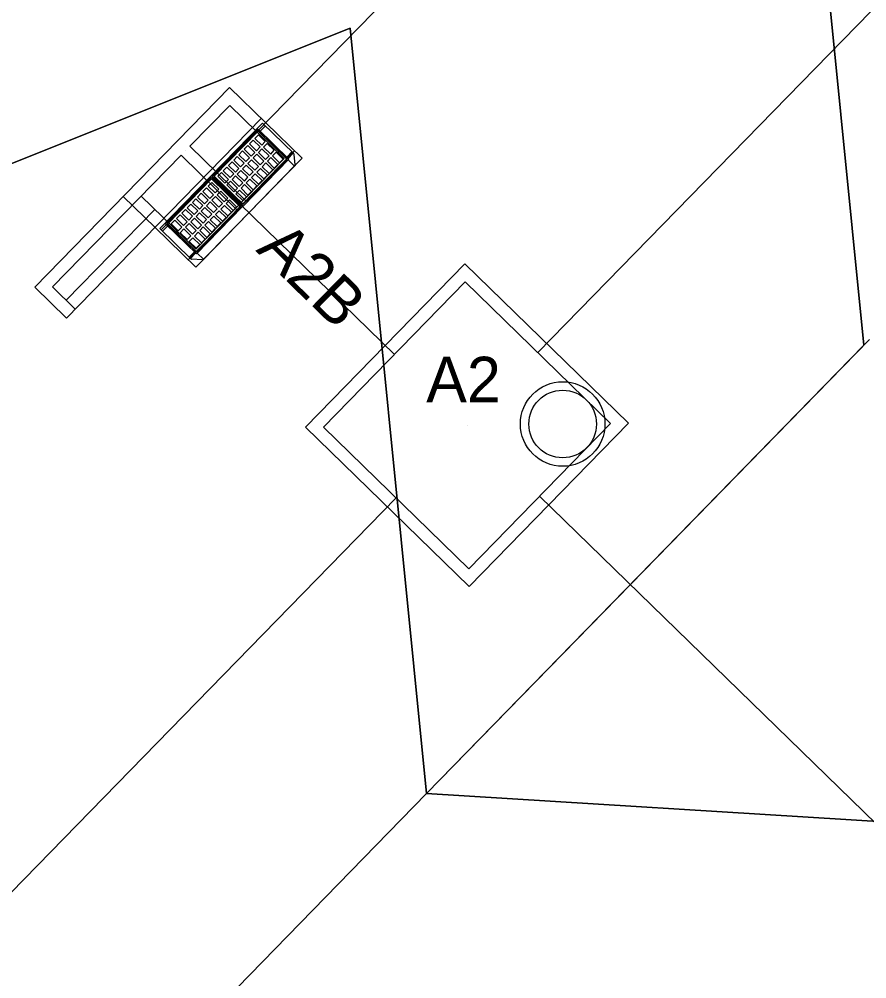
# Model space of a CAD drawing. Extents: x 2251012 to 2259557, y 13786786 to 13792525.
# Drawn here: x 2254858.7 to 2254892.11, y 13790745.59 to 13790783.43 of the extents above; entities that cross this region are included whole.
import ezdxf

# ---------------------------------------------------------------- set-up
doc = ezdxf.new("R2010")
doc.units = 0
for name, color, linetype in [('D_BOXES_1', 7, 'Continuous'), ('D_DRAIN_MISC', 7, 'Continuous'), ('D_DRAIN_NOTES_1', 7, 'Continuous'), ('D_DRN_AREA_X', 7, 'Continuous'), ('D_INLET_1', 7, 'Continuous'), ('D_PIPES_1', 7, 'Continuous')]:
    doc.layers.add(name, color=color, linetype=linetype)

msp = doc.modelspace()

# ---------------------------------------------------------------- linework, layer by layer
at = {"layer": 'D_BOXES_1'}
for p, q in [((2254879.145, 13790770.287), (2254992.252, 13790886.265)), ((2254701.107, 13790587.73), (2254873.56, 13790764.56))]:
    msp.add_line(p, q, dxfattribs=at)
at = {"layer": 'D_DRAIN_MISC'}
for p, q in [((2254868.075, 13790778.988), (2254868.075, 13790778.988)), ((2254865.256, 13790778.245), (2254865.256, 13790778.245)), ((2254866.151, 13790777.373), (2254866.151, 13790777.373)), ((2254867.404, 13790776.151), (2254867.404, 13790776.151)), ((2254864.584, 13790775.408), (2254864.584, 13790775.408)), ((2254873.489, 13790770.216), (2254873.489, 13790770.216)), ((2254879.145, 13790770.287), (2254879.145, 13790770.287)), ((2254876.353, 13790767.423), (2254876.353, 13790767.423)), ((2254873.56, 13790764.56), (2254873.56, 13790764.56)), ((2254879.216, 13790764.631), (2254879.216, 13790764.631))]:
    msp.add_line(p, q, dxfattribs=at)
at = {"layer": 'D_DRN_AREA_X'}
for p, q in [((2254889.021, 13790800.465), (2254891.998, 13790770.575)), ((2254891.998, 13790770.575), (2254889.021, 13790800.465)), ((2254871.751, 13790783.085), (2254856.243, 13790776.881)), ((2254856.243, 13790776.881), (2254871.751, 13790783.085)), ((2254874.758, 13790752.898), (2254871.751, 13790783.085)), ((2254871.751, 13790783.085), (2254874.758, 13790752.898)), ((2254892.224, 13790770.808), (2254881.752, 13790760.069)), ((2254891.998, 13790770.575), (2254892.224, 13790770.808)), ((2254874.758, 13790752.898), (2254891.998, 13790770.575)), ((2254881.752, 13790760.069), (2254874.758, 13790752.898)), ((2254874.758, 13790752.898), (2254731.655, 13790606.163)), ((2254832.878, 13790709.955), (2254874.758, 13790752.898)), ((2254905.36, 13790751.006), (2254874.758, 13790752.898)), ((2254874.758, 13790752.898), (2254905.36, 13790751.006))]:
    msp.add_line(p, q, dxfattribs=at)
at = {"layer": 'D_INLET_1'}
for p, q in [((2254866.993, 13790780.742), (2254859.312, 13790772.867)), ((2254869.856, 13790777.949), (2254866.993, 13790780.742)), ((2254867.001, 13790780.035), (2254865.43, 13790778.424)), ((2254869.149, 13790777.941), (2254867.001, 13790780.035)), ((2254868.245, 13790779.52), (2254860.565, 13790771.645)), ((2254868.294, 13790779.334), (2254865.202, 13790776.164)), ((2254868.115, 13790779.1), (2254866.309, 13790777.248)), ((2254869.333, 13790777.913), (2254868.115, 13790779.1)), ((2254868.149, 13790779.067), (2254868.353, 13790779.276)), ((2254868.2, 13790779.017), (2254868.404, 13790779.226)), ((2254869.523, 13790778.135), (2254868.294, 13790779.334)), ((2254868.12, 13790779.037), (2254866.372, 13790777.244)), ((2254868.118, 13790779.017), (2254866.391, 13790777.247)), ((2254868.129, 13790778.875), (2254867.987, 13790778.73)), ((2254867.987, 13790778.73), (2254868.261, 13790778.462)), ((2254869.25, 13790777.913), (2254868.118, 13790779.017)), ((2254869.27, 13790777.916), (2254868.12, 13790779.037)), ((2254868.403, 13790778.608), (2254868.129, 13790778.875)), ((2254865.43, 13790778.424), (2254867.635, 13790776.274)), ((2254867.714, 13790778.45), (2254867.572, 13790778.304)), ((2254867.572, 13790778.304), (2254867.846, 13790778.036)), ((2254867.714, 13790778.45), (2254867.988, 13790778.182)), ((2254867.921, 13790778.663), (2254867.779, 13790778.517)), ((2254867.779, 13790778.517), (2254868.054, 13790778.249)), ((2254867.921, 13790778.663), (2254868.196, 13790778.395)), ((2254868.054, 13790778.249), (2254868.196, 13790778.395)), ((2254868.13, 13790778.174), (2254868.272, 13790778.32)), ((2254868.261, 13790778.462), (2254868.403, 13790778.608)), ((2254868.272, 13790778.32), (2254868.549, 13790778.05)), ((2254868.338, 13790778.387), (2254868.48, 13790778.533)), ((2254868.338, 13790778.387), (2254868.615, 13790778.117)), ((2254868.757, 13790778.263), (2254868.48, 13790778.533)), ((2254865.081, 13790778.066), (2254860.019, 13790772.876)), ((2254865.081, 13790778.066), (2254867.286, 13790775.916)), ((2254869.555, 13790778.243), (2254865.366, 13790773.947)), ((2254869.149, 13790777.941), (2254865.658, 13790774.361)), ((2254869.853, 13790777.952), (2254865.664, 13790773.657)), ((2254869.856, 13790777.949), (2254865.667, 13790773.654)), ((2254867.298, 13790778.024), (2254867.156, 13790777.878)), ((2254867.298, 13790778.024), (2254867.573, 13790777.756)), ((2254867.506, 13790778.237), (2254867.364, 13790778.091)), ((2254867.364, 13790778.091), (2254867.639, 13790777.823)), ((2254867.506, 13790778.237), (2254867.781, 13790777.969)), ((2254869.27, 13790777.916), (2254867.521, 13790776.123)), ((2254867.524, 13790776.143), (2254869.25, 13790777.913)), ((2254869.333, 13790777.913), (2254867.526, 13790776.06)), ((2254867.639, 13790777.823), (2254867.781, 13790777.969)), ((2254867.846, 13790778.036), (2254867.988, 13790778.182)), ((2254867.923, 13790777.962), (2254868.065, 13790778.107)), ((2254867.923, 13790777.962), (2254868.2, 13790777.692)), ((2254868.065, 13790778.107), (2254868.342, 13790777.837)), ((2254868.13, 13790778.174), (2254868.407, 13790777.905)), ((2254868.407, 13790777.905), (2254868.549, 13790778.05)), ((2254868.484, 13790777.83), (2254868.626, 13790777.975)), ((2254868.615, 13790778.117), (2254868.757, 13790778.263)), ((2254868.626, 13790777.975), (2254868.9, 13790777.708)), ((2254868.691, 13790778.043), (2254868.833, 13790778.188)), ((2254868.691, 13790778.043), (2254868.966, 13790777.775)), ((2254869.108, 13790777.92), (2254868.833, 13790778.188)), ((2254868.966, 13790777.775), (2254869.108, 13790777.92)), ((2254869.248, 13790777.996), (2254869.452, 13790778.205)), ((2254869.299, 13790777.946), (2254869.503, 13790778.155)), ((2254869.578, 13790777.691), (2254869.539, 13790778.104)), ((2254869.567, 13790777.659), (2254865.95, 13790773.95)), ((2254866.883, 13790777.598), (2254866.741, 13790777.453)), ((2254866.883, 13790777.598), (2254867.158, 13790777.33)), ((2254867.091, 13790777.811), (2254866.949, 13790777.665)), ((2254866.949, 13790777.665), (2254867.223, 13790777.398)), ((2254867.091, 13790777.811), (2254867.365, 13790777.543)), ((2254867.156, 13790777.878), (2254867.431, 13790777.611)), ((2254867.223, 13790777.398), (2254867.365, 13790777.543)), ((2254867.431, 13790777.611), (2254867.573, 13790777.756)), ((2254867.508, 13790777.536), (2254867.65, 13790777.681)), ((2254867.508, 13790777.536), (2254867.784, 13790777.266)), ((2254867.65, 13790777.681), (2254867.926, 13790777.412)), ((2254869.238, 13790777.86), (2254867.664, 13790776.246)), ((2254867.715, 13790777.749), (2254867.857, 13790777.894)), ((2254867.715, 13790777.749), (2254867.992, 13790777.479)), ((2254867.857, 13790777.894), (2254868.134, 13790777.624)), ((2254867.992, 13790777.479), (2254868.134, 13790777.624)), ((2254868.069, 13790777.404), (2254868.211, 13790777.55)), ((2254868.2, 13790777.692), (2254868.342, 13790777.837)), ((2254868.211, 13790777.55), (2254868.485, 13790777.282)), ((2254868.276, 13790777.617), (2254868.418, 13790777.763)), ((2254868.276, 13790777.617), (2254868.551, 13790777.349)), ((2254868.418, 13790777.763), (2254868.693, 13790777.495)), ((2254868.484, 13790777.83), (2254868.758, 13790777.562)), ((2254868.758, 13790777.562), (2254868.9, 13790777.708)), ((2254869.304, 13790777.883), (2254869.551, 13790777.642)), ((2254864.473, 13790775.365), (2254866.28, 13790777.218)), ((2254864.536, 13790775.362), (2254866.285, 13790777.155)), ((2254867.497, 13790776.03), (2254866.28, 13790777.218)), ((2254867.434, 13790776.034), (2254866.285, 13790777.155)), ((2254867.526, 13790776.06), (2254866.309, 13790777.248)), ((2254867.521, 13790776.123), (2254866.372, 13790777.244)), ((2254867.524, 13790776.143), (2254866.391, 13790777.247)), ((2254866.676, 13790777.385), (2254866.534, 13790777.24)), ((2254866.808, 13790776.972), (2254866.534, 13790777.24)), ((2254866.676, 13790777.385), (2254866.95, 13790777.118)), ((2254866.741, 13790777.453), (2254867.016, 13790777.185)), ((2254867.016, 13790777.185), (2254867.158, 13790777.33)), ((2254867.092, 13790777.11), (2254867.234, 13790777.256)), ((2254867.234, 13790777.256), (2254867.511, 13790776.986)), ((2254867.3, 13790777.323), (2254867.442, 13790777.469)), ((2254867.3, 13790777.323), (2254867.577, 13790777.053)), ((2254867.442, 13790777.469), (2254867.719, 13790777.199)), ((2254867.577, 13790777.053), (2254867.719, 13790777.199)), ((2254867.784, 13790777.266), (2254867.926, 13790777.412)), ((2254867.861, 13790777.191), (2254868.003, 13790777.337)), ((2254867.861, 13790777.191), (2254868.136, 13790776.923)), ((2254868.003, 13790777.337), (2254868.278, 13790777.069)), ((2254868.069, 13790777.404), (2254868.343, 13790777.136)), ((2254868.343, 13790777.136), (2254868.485, 13790777.282)), ((2254868.551, 13790777.349), (2254868.693, 13790777.495)), ((2254864.556, 13790775.365), (2254866.282, 13790777.135)), ((2254865.944, 13790776.635), (2254866.086, 13790776.78)), ((2254866.086, 13790776.78), (2254866.36, 13790776.513)), ((2254866.151, 13790776.848), (2254866.293, 13790776.993)), ((2254866.151, 13790776.848), (2254866.426, 13790776.58)), ((2254867.415, 13790776.031), (2254866.282, 13790777.135)), ((2254866.568, 13790776.725), (2254866.293, 13790776.993)), ((2254866.808, 13790776.972), (2254866.95, 13790777.118)), ((2254866.885, 13790776.897), (2254867.027, 13790777.043)), ((2254867.162, 13790776.627), (2254866.885, 13790776.897)), ((2254867.027, 13790777.043), (2254867.304, 13790776.773)), ((2254867.092, 13790777.11), (2254867.369, 13790776.84)), ((2254867.162, 13790776.627), (2254867.304, 13790776.773)), ((2254867.369, 13790776.84), (2254867.511, 13790776.986)), ((2254867.446, 13790776.765), (2254867.588, 13790776.911)), ((2254867.588, 13790776.911), (2254867.862, 13790776.643)), ((2254867.653, 13790776.978), (2254867.795, 13790777.124)), ((2254867.653, 13790776.978), (2254867.928, 13790776.71)), ((2254867.795, 13790777.124), (2254868.07, 13790776.856)), ((2254867.928, 13790776.71), (2254868.07, 13790776.856)), ((2254868.136, 13790776.923), (2254868.278, 13790777.069)), ((2254864.056, 13790775.225), (2254862.803, 13790776.447)), ((2254865.658, 13790774.361), (2254863.51, 13790776.456)), ((2254865.736, 13790776.422), (2254865.878, 13790776.567)), ((2254865.736, 13790776.422), (2254866.011, 13790776.154)), ((2254865.878, 13790776.567), (2254866.153, 13790776.3)), ((2254865.944, 13790776.635), (2254866.218, 13790776.367)), ((2254866.36, 13790776.513), (2254866.218, 13790776.367)), ((2254866.437, 13790776.438), (2254866.295, 13790776.292)), ((2254866.568, 13790776.725), (2254866.426, 13790776.58)), ((2254866.437, 13790776.438), (2254866.714, 13790776.168)), ((2254866.644, 13790776.651), (2254866.502, 13790776.505)), ((2254866.502, 13790776.505), (2254866.779, 13790776.235)), ((2254866.921, 13790776.381), (2254866.644, 13790776.651)), ((2254867.238, 13790776.553), (2254867.38, 13790776.698)), ((2254867.513, 13790776.285), (2254867.238, 13790776.553)), ((2254867.38, 13790776.698), (2254867.655, 13790776.43)), ((2254867.446, 13790776.765), (2254867.72, 13790776.498)), ((2254867.513, 13790776.285), (2254867.655, 13790776.43)), ((2254867.72, 13790776.498), (2254867.862, 13790776.643)), ((2254865.202, 13790776.164), (2254864.244, 13790775.181)), ((2254865.321, 13790775.996), (2254865.463, 13790776.142)), ((2254865.463, 13790776.142), (2254865.737, 13790775.874)), ((2254865.528, 13790776.209), (2254865.67, 13790776.355)), ((2254865.528, 13790776.209), (2254865.803, 13790775.941)), ((2254865.67, 13790776.355), (2254865.945, 13790776.087)), ((2254865.686, 13790774.241), (2254867.434, 13790776.034)), ((2254867.415, 13790776.031), (2254865.688, 13790774.261)), ((2254865.691, 13790774.178), (2254867.497, 13790776.03)), ((2254865.945, 13790776.087), (2254865.803, 13790775.941)), ((2254866.153, 13790776.3), (2254866.011, 13790776.154)), ((2254866.229, 13790776.225), (2254866.087, 13790776.079)), ((2254866.087, 13790776.079), (2254866.364, 13790775.809)), ((2254866.229, 13790776.225), (2254866.506, 13790775.955)), ((2254866.295, 13790776.292), (2254866.572, 13790776.022)), ((2254866.714, 13790776.168), (2254866.572, 13790776.022)), ((2254866.79, 13790776.093), (2254866.648, 13790775.948)), ((2254866.921, 13790776.381), (2254866.779, 13790776.235)), ((2254866.79, 13790776.093), (2254867.065, 13790775.825)), ((2254866.998, 13790776.306), (2254866.856, 13790776.16)), ((2254866.856, 13790776.16), (2254867.13, 13790775.893)), ((2254867.272, 13790776.038), (2254866.998, 13790776.306)), ((2254867.272, 13790776.038), (2254867.13, 13790775.893)), ((2254864.047, 13790775.932), (2254860.556, 13790772.352)), ((2254864.906, 13790775.57), (2254865.048, 13790775.716)), ((2254865.048, 13790775.716), (2254865.322, 13790775.448)), ((2254865.113, 13790775.783), (2254865.255, 13790775.929)), ((2254865.113, 13790775.783), (2254865.388, 13790775.515)), ((2254865.255, 13790775.929), (2254865.53, 13790775.661)), ((2254865.321, 13790775.996), (2254865.595, 13790775.728)), ((2254865.53, 13790775.661), (2254865.388, 13790775.515)), ((2254865.737, 13790775.874), (2254865.595, 13790775.728)), ((2254865.814, 13790775.799), (2254865.672, 13790775.654)), ((2254865.672, 13790775.654), (2254865.949, 13790775.384)), ((2254867.315, 13790775.888), (2254865.741, 13790774.274)), ((2254865.814, 13790775.799), (2254866.091, 13790775.529)), ((2254866.022, 13790776.012), (2254865.88, 13790775.866)), ((2254865.88, 13790775.866), (2254866.156, 13790775.597)), ((2254866.022, 13790776.012), (2254866.298, 13790775.742)), ((2254866.298, 13790775.742), (2254866.156, 13790775.597)), ((2254866.375, 13790775.667), (2254866.233, 13790775.522)), ((2254866.506, 13790775.955), (2254866.364, 13790775.809)), ((2254866.375, 13790775.667), (2254866.65, 13790775.4)), ((2254866.583, 13790775.88), (2254866.441, 13790775.735)), ((2254866.441, 13790775.735), (2254866.715, 13790775.467)), ((2254866.583, 13790775.88), (2254866.857, 13790775.613)), ((2254866.648, 13790775.948), (2254866.923, 13790775.68)), ((2254867.065, 13790775.825), (2254866.923, 13790775.68)), ((2254864.507, 13790775.332), (2254864.303, 13790775.123)), ((2254864.558, 13790775.282), (2254864.354, 13790775.073)), ((2254865.691, 13790774.178), (2254864.473, 13790775.365)), ((2254865.686, 13790774.241), (2254864.536, 13790775.362)), ((2254865.688, 13790774.261), (2254864.556, 13790775.365)), ((2254864.698, 13790775.358), (2254864.84, 13790775.503)), ((2254864.973, 13790775.09), (2254864.698, 13790775.358)), ((2254864.84, 13790775.503), (2254865.115, 13790775.235)), ((2254864.906, 13790775.57), (2254865.18, 13790775.303)), ((2254865.322, 13790775.448), (2254865.18, 13790775.303)), ((2254865.399, 13790775.373), (2254865.257, 13790775.228)), ((2254865.399, 13790775.373), (2254865.676, 13790775.104)), ((2254865.606, 13790775.586), (2254865.464, 13790775.441)), ((2254865.464, 13790775.441), (2254865.741, 13790775.171)), ((2254865.606, 13790775.586), (2254865.883, 13790775.316)), ((2254865.883, 13790775.316), (2254865.741, 13790775.171)), ((2254866.091, 13790775.529), (2254865.949, 13790775.384)), ((2254866.167, 13790775.455), (2254866.025, 13790775.309)), ((2254866.025, 13790775.309), (2254866.3, 13790775.041)), ((2254866.167, 13790775.455), (2254866.442, 13790775.187)), ((2254866.233, 13790775.522), (2254866.508, 13790775.254)), ((2254866.65, 13790775.4), (2254866.508, 13790775.254)), ((2254866.857, 13790775.613), (2254866.715, 13790775.467)), ((2254865.667, 13790773.654), (2254864.056, 13790775.225)), ((2254865.473, 13790773.982), (2254864.244, 13790775.181)), ((2254865.115, 13790775.235), (2254864.973, 13790775.09)), ((2254865.191, 13790775.161), (2254865.049, 13790775.015)), ((2254865.326, 13790774.745), (2254865.049, 13790775.015)), ((2254865.191, 13790775.161), (2254865.468, 13790774.891)), ((2254865.257, 13790775.228), (2254865.534, 13790774.958)), ((2254865.468, 13790774.891), (2254865.326, 13790774.745)), ((2254865.676, 13790775.104), (2254865.534, 13790774.958)), ((2254865.752, 13790775.029), (2254865.61, 13790774.883)), ((2254865.61, 13790774.883), (2254865.885, 13790774.615)), ((2254865.752, 13790775.029), (2254866.027, 13790774.761)), ((2254865.96, 13790775.242), (2254865.818, 13790775.096)), ((2254865.818, 13790775.096), (2254866.092, 13790774.828)), ((2254865.96, 13790775.242), (2254866.234, 13790774.974)), ((2254866.234, 13790774.974), (2254866.092, 13790774.828)), ((2254866.442, 13790775.187), (2254866.3, 13790775.041)), ((2254865.545, 13790774.816), (2254865.403, 13790774.67)), ((2254865.677, 13790774.403), (2254865.403, 13790774.67)), ((2254865.545, 13790774.816), (2254865.819, 13790774.548)), ((2254865.819, 13790774.548), (2254865.677, 13790774.403)), ((2254866.027, 13790774.761), (2254865.885, 13790774.615)), ((2254865.606, 13790774.261), (2254865.402, 13790774.052)), ((2254865.657, 13790774.211), (2254865.453, 13790774.002)), ((2254865.72, 13790774.208), (2254865.967, 13790773.967)), ((2254865.919, 13790773.939), (2254865.505, 13790773.968)), ((2254869.989, 13790767.344), (2254876.273, 13790773.787)), ((2254876.273, 13790773.787), (2254882.716, 13790767.503)), ((2254870.696, 13790767.352), (2254876.282, 13790773.08)), ((2254876.282, 13790773.08), (2254882.009, 13790767.494)), ((2254859.312, 13790772.867), (2254860.565, 13790771.645)), ((2254860.019, 13790772.876), (2254860.914, 13790772.003)), ((2254876.432, 13790761.06), (2254869.989, 13790767.344)), ((2254876.423, 13790761.767), (2254870.696, 13790767.352)), ((2254882.009, 13790767.494), (2254876.423, 13790761.767)), ((2254882.716, 13790767.503), (2254876.432, 13790761.06))]:
    msp.add_line(p, q, dxfattribs=at)
for radius in [1.666, 1.333]:
    msp.add_circle((2254880.124, 13790767.471), radius, dxfattribs=at)
for centre, start_param, end_param in [((2254869.494, 13790778.105), 0.80294, 1.570796), ((2254869.533, 13790777.692), 0, 0.80294), ((2254865.502, 13790774.012), 4.712389, 5.480245), ((2254865.916, 13790773.983), 5.480245, 6.283185)]:
    msp.add_ellipse(centre, major_axis=(0.0341, -0.0332), ratio=0.877193, start_param=start_param, end_param=end_param, dxfattribs=at)
at = {"layer": 'D_PIPES_1'}
for p, q in [((2254882.039, 13790793.306), (2254868.075, 13790778.988)), ((2254867.404, 13790776.151), (2254873.489, 13790770.216)), ((2254898.188, 13790746.129), (2254879.216, 13790764.631))]:
    msp.add_line(p, q, dxfattribs=at)

# ---------------------------------------------------------------- texts
at = {"layer": 'D_DRAIN_NOTES_1'}
msp.add_text('A2B', height=1.8, rotation=315.7179, dxfattribs=at).set_placement((2254868.002, 13790774.31))
msp.add_text('A2', height=1.8, dxfattribs=at).set_placement((2254874.744, 13790768.323))

doc.saveas('drawing.dxf')
